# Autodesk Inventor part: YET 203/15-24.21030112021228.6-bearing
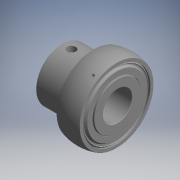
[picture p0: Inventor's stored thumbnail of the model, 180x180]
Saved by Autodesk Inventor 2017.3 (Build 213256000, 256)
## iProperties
Part Number: YET 203/15-24.21030112021228.6-bearing
Material: Generic
Catalog Web Link: www.cadenas.de
Description: ayf_001hc_hh_hy_bearing-Y-bearings
Vendor: SKF
Document SubType Name: Modeling
Designer: partserver
Manufacturer: SKF
Mass: 13.4334 g
Surface Area: 122.387 cm^2
Volume: 13.4334 cm^3
Density: 1 g/cm^3
Appearance: PSOLRGB-175-175-175
Category: PARTsolutions
Company: SKF
Title: YET 203/15-24.21030112021228.6-bearing
Author: Cadenas PARTsolutions
Comments: Y-bearings
PSOL_IDENT_0: {$CADENAS_DATA\23d-libs\skf\bearings_units_and_housings\bearing_units\ball_bearing_units\y-units\y-b
PSOL_IDENT_1: earing_square_flanged_units_parts\ayf_001hc_hh_hy_bearing.prj},235 {VTYP=3D},{NB=YET 203/15-24.21030
PSOL_IDENT_2: 112021228.6-bearing},{LINA=YET 203/15-24.21030112021228.6-bearing},{NN=ayf_001hc_hh_hy_bearing},{DAT
PSOL_IDENT_3: E=20.08.2020 13:45:20},{GEOMDATE=29.07.2020 17:09:33},{VERSION=},{LINEID=2150},{WBVAR=},{WBNUMERIC=}
PSOL_IDENT_4: {NB=YET 203/15-24.21030112021228.6-bearing},{LINA=YET 203/15-24.21030112021228.6-bearing},{KT=DUMM
PSOL_IDENT_5: Y},{PRODUCTID=103011202},{DESIGNATION=YET 203/15},{DD=15.0000},{D=40},{B=19.100},{C=12.000},{PITCH=2
PSOL_IDENT_6: 8.500},{DW=6.747},{FO=IEC_BBY_005},{DESIGN=ybrg2},{B1=28.600},{LM=Eccentric locking collar},{DES=Inn
PSOL_IDENT_7: er ring extended on one side},{PS=For agricultural applications},{MAT=},{SS=Standard seals},{UNIT=Me
PSOL_IDENT_8: tric},{G=MIN},{DD1=24.20},{DD2=27.20},{DD3=MIN},{B3=13.500},{B4=4.8},{BB4=MIN},{R12=0.3},{R12X=0},{S
PSOL_IDENT_9: S1=22.100},{NOTE=},{DG=MIN},{E=3.600},{F=1.300},{RG=MIN},{LOAD1=9.560},{LOAD2=4.750},{LOAD3=0.200},{
PSOL_IDENT_10: SPEED2=9500},{FF0=13},{BF=1},{A15=500000},{A8=400000},{A4=300000},{BETA=1.89},{SBT1=0.094},{SBT2=},{
PSOL_IDENT_11: RF1=0.00000039},{RF2=1.7},{SF1=0.00323},{SF2=36.5},{KZ=3.1},{II=1},{Z=8},{SG=VT307},{MASS=0.12},{G2=
PSOL_IDENT_12: M6x0.75},{HEX=3.000},{RTT=4},{MKIT=},{AS=},{TANGLE=},{SLEEVE=},{SRING=RIS 203},{FPC=RBC17_YBRG_003},
PSOL_IDENT_13: {POPI=1},{NOUN=N020},{NOUNDES=Ball bearing},{MOD=M200},{MODDES=Radial deep groove},{YZ=12.1},{PIM=YE
PSOL_IDENT_14: T 203/15},{LNDD11=MIN},{LUB3=0},{BZ=0.3502},{SDALG=h},{YRZ=17.6235},{SHAPE=1},{LNB1HM11=0},{LWM=0},{
PSOL_IDENT_15: TYPEID=103011},{LUBGR2=0},{LOCKNUT=},{LOCKDEVICE=},{LNB=MIN},{BB=MIN},{LNB1=MIN},{S1ALG=0},{HH=MIN},
PSOL_IDENT_16: {LDB=MIN},{LDDD1=MIN},{LDDD2=MIN},{LDM=MIN},{LDFF=MIN},{TP=4},{LNBHM11=0},{BBHM11=0},{LNDD1HM11=0},{
PSOL_IDENT_17: HELP=3},{HHHM11=0},{LUBGR1=0},{LWV=0},{S2=0},{LUB2=1},{BZ1=0.000},{HEX2=}
NB: YET 203/15-24.21030112021228.6-bearing
NN: ayf_001hc_hh_hy_bearing
NT: Y-bearings
NBSYN: $DESIGNATION.-$DD1.$PRODUCTID.$C.$B1.-bearing
LINA: YET 203/15-24.21030112021228.6-bearing
CATALOG: SKF
DESIGNATION: YET 203/15
DD: 15
D: 40
B: 19.1
C: 12
B1: 28.6
DD1: 24.2
LOAD1: 9.56
LOAD2: 4.75
LOAD3: 0.2
SPEED2: 9500
SUPPLIER: SKF
ARTICLENO: YET 203/15-24.21030112021228.6-bearing
BOMINFO: YET 203/15-24.21030112021228.6-bearing
CREATOR: CADENAS GmbH
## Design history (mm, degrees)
sketch "Sketch_1"
  geometry: L1 (12.3, 0)-(-6.2, 0); L2 (-6.2, 7.5)-(12.3, 7.5); L3 (12.6, 7.8)-(12.6, 11.45); L4 (12.45, 11.6)-(8.6, 11.6); L5 (8.6, 11.6)-(8.6, 12.1); L6 (8.6, 12.1)-(2.6, 12.1); L7 (-2.6, 12.1)-(-6.35, 12.1); L8 (-6.5, 11.95)-(-6.5, 7.8); A1 r 0.3 centre (-6.2, 7.8) between (-6.5, 7.8) and (-6.2, 7.5); A2 r 0.3 centre (12.3, 7.8) between (12.3, 7.5) and (12.6, 7.8); A3 r 0.15 centre (12.45, 11.45) between (12.6, 11.45) and (12.45, 11.6); A4 r 3.374 centre (0, 14.25) between (-2.6, 12.1) and (2.6, 12.1); A5 r 0.15 centre (-6.35, 11.95) between (-6.35, 12.1) and (-6.5, 11.95)
  constraints: 16 end point, 10 point on circle, 5 centre point
revolve "Revolution1" sketch "Sketch_1" stored, may be unused: angle "d0" = 360 deg
sketch "Sketch_4"
  geometry: L1 (50, 0)-(-50, 0); L2 (-6, 15.235)-(-6, 12.431); L3 (-6, 12.431)-(-5.65, 12.431); L4 (-5.65, 12.431)-(-5.65, 15.059); L5 (-5.65, 15.059)-(-4.88, 15.636); L6 (-4.88, 15.636)-(-4.838, 15.58); L7 (-4.838, 15.58)-(-5.58, 15.024); L8 (-5.58, 15.024)-(-5.58, 12.597); L9 (-5.58, 12.597)-(-4.961, 12.597); L10 (-4.961, 12.597)-(-5.066, 12.1); L11 (-5.066, 12.1)-(-4.716, 12.1); L12 (-4.716, 12.1)-(-4.599, 12.652); L13 (-4.599, 12.652)-(-4.599, 13.205); L14 (-4.599, 13.205)-(-5.066, 13.757); L15 (-5.066, 13.757)-(-5.066, 14.862); L16 (-5.066, 14.862)-(-4.599, 15.414); L17 (-4.599, 15.414)-(-4.599, 17.573); L18 (-4.649, 17.623)-(-4.899, 17.623); L19 (-4.949, 17.573)-(-5.568, 16.836); L20 (-5.568, 16.836)-(-5.3, 16.611); L21 (-5.3, 16.611)-(-4.949, 17.029); L22 (-4.949, 17.029)-(-4.949, 16.021); L23 (-4.949, 16.021)-(-6, 15.235); A1 r 0.05 centre (-4.649, 17.573) between (-4.599, 17.573) and (-4.649, 17.623); A2 r 0.05 centre (-4.899, 17.573) between (-4.899, 17.623) and (-4.949, 17.573)
  constraints: 46 end point, 4 point on circle, 2 centre point
revolve "Revolution2" sketch "Sketch_4" stored, may be unused: angle "d1" = 360 deg
sketch "Sketch_9"
  geometry: L1 (50, 0)-(-50, 0); L2 (4.599, 17.573)-(4.599, 15.414); L3 (4.599, 15.414)-(5.066, 14.862); L4 (5.066, 14.862)-(5.066, 13.757); L5 (5.066, 13.757)-(4.599, 13.205); L6 (4.599, 13.205)-(4.599, 12.652); L7 (4.599, 12.652)-(4.716, 12.1); L8 (4.716, 12.1)-(5.066, 12.1); L9 (5.066, 12.1)-(4.961, 12.597); L10 (4.961, 12.597)-(5.58, 12.597); L11 (5.58, 12.597)-(5.58, 15.024); L12 (5.58, 15.024)-(4.838, 15.58); L13 (4.838, 15.58)-(4.88, 15.636); L14 (4.88, 15.636)-(5.65, 15.059); L15 (5.65, 15.059)-(5.65, 12.431); L16 (5.65, 12.431)-(6, 12.431); L17 (6, 12.431)-(6, 15.235); L18 (6, 15.235)-(4.949, 16.021); L19 (4.949, 16.021)-(4.949, 17.029); L20 (4.949, 17.029)-(5.3, 16.611); L21 (5.3, 16.611)-(5.568, 16.836); L22 (5.568, 16.836)-(4.949, 17.573); L23 (4.899, 17.623)-(4.649, 17.623); A1 r 0.05 centre (4.899, 17.573) between (4.949, 17.573) and (4.899, 17.623); A2 r 0.05 centre (4.649, 17.573) between (4.649, 17.623) and (4.599, 17.573)
  constraints: 46 end point, 4 point on circle, 2 centre point
revolve "Revolution3" sketch "Sketch_9" stored, may be unused: angle "d2" = 360 deg
sketch "Sketch_14"
  geometry: L1 (6, 0)-(-6, 0); L2 (-6, 17.448)-(-5.023, 17.448); L3 (-5.023, 17.448)-(-4.919, 17.525); L4 (-4.569, 17.44)-(-4.464, 16.949); L5 (-4.464, 16.949)-(-2.024, 16.949); L6 (2.024, 16.949)-(4.464, 16.949); L7 (4.464, 16.949)-(4.569, 17.44); L8 (4.889, 17.555)-(5.023, 17.448); L9 (5.023, 17.448)-(6, 17.448); L10 (6, 17.448)-(6, 19.005); L11 (-6, 19.005)-(-6, 17.448); A1 r 0.2 centre (-4.764, 17.398) between (-4.569, 17.44) and (-4.919, 17.525); A2 r 3.373 centre (0, 14.25) between (2.024, 16.949) and (-2.024, 16.949); A3 r 0.2 centre (4.764, 17.398) between (4.889, 17.555) and (4.569, 17.44); A4 r 0.1 centre (5.9, 19.005) between (6, 19.005) and (5.93, 19.101); A5 r 20 centre (0, 0) between (5.93, 19.101) and (-5.93, 19.101); A6 r 0.1 centre (-5.9, 19.005) between (-5.93, 19.101) and (-6, 19.005)
  constraints: 22 end point, 12 point on circle, 6 centre point
revolve "Revolution4" sketch "Sketch_14" stored, may be unused: angle "d3" = 360 deg
sketch "Sketch_15"
  geometry: L1 (-2.1, 21)-(-2.1, 14.25); L2 (-2.1, 14.25)-(-2.75, 14.25); L3 (-2.75, 14.25)-(-2.75, 21); L4 (-2.75, 21)-(-2.1, 21); L5 (-2.1, 21)-(-2.1, 14.25)
  constraints: 10 end point
revolve "Revolution5" sketch "Sketch_15" stored, may be unused: angle "d4" = 360 deg
sketch "Sketch_16"
  geometry: L1 (-3.6, 21)-(-3.6, 14.25); L2 (-3.6, 14.25)-(-4.25, 14.25); L3 (-4.25, 14.25)-(-4.25, 21); L4 (-4.25, 21)-(-3.6, 21); L5 (-3.6, 21)-(-3.6, 14.25)
  constraints: 10 end point
revolve "Revolution6" sketch "Sketch_16" stored, may be unused: angle "d5" = 360 deg
sketch "Sketch_17"
  geometry: L1 (21.8, 0)-(12.9, 0); L2 (8.6, 13.3)-(8.6, 12.25); L3 (8.6, 12.25)-(8.75, 12.1); L4 (8.75, 12.1)-(12.6, 12.1); L5 (12.6, 12.1)-(12.6, 7.8); L6 (12.6, 7.8)-(12.9, 7.5); L7 (12.9, 7.5)-(21.8, 7.5); L8 (21.8, 7.5)-(22.1, 7.8); L9 (22.1, 7.8)-(22.1, 13.45); L10 (21.95, 13.6)-(8.9, 13.6); A1 r 0.15 centre (21.95, 13.45) between (22.1, 13.45) and (21.95, 13.6); A2 r 0.3 centre (8.9, 13.3) between (8.9, 13.6) and (8.6, 13.3)
  constraints: 20 end point, 4 point on circle, 2 centre point
revolve "Revolution7" sketch "Sketch_17" stored, may be unused: angle "d6" = 360 deg
sketch "Sketch_18"
  geometry: L1 (17.3, 7.5)-(17.3, 13.905); L2 (17.3, 13.905)-(20.3, 13.905); L3 (20.3, 13.905)-(20.3, 7.5); L4 (20.3, 7.5)-(17.3, 7.5); L5 (17.3, 7.5)-(17.3, 13.905)
  constraints: 10 end point
revolve "Revolution8" sketch "Sketch_18" stored, may be unused: angle "d7" = 360 deg
sketch "Sketch_19"
  geometry: L1 (-1.5, -0.866)-(0, -1.732); L2 (0, -1.732)-(1.5, -0.866); L3 (1.5, -0.866)-(1.5, 0.866); L4 (1.5, 0.866)-(0, 1.732); L5 (0, 1.732)-(-1.5, 0.866); L6 (-1.5, 0.866)-(-1.5, -0.866)
  constraints: 12 end point
extrude "Extrusion1" cut sketch "Sketch_19" distance "d8" = 0.61; taper "d9" = 0 deg
sketch "Sketch_20"
  geometry: L1 (-17.3, -9.303)-(-17.3, -13.905); L2 (-17.3, -13.905)-(-19.46, -13.905); L3 (-19.46, -13.905)-(-19.46, -10.55); L4 (-19.46, -10.55)-(-17.3, -9.303); L5 (-17.3, -9.303)-(-17.3, -13.905)
  constraints: 10 end point
revolve "Revolution9" sketch "Sketch_20" stored, may be unused: angle "d10" = 360 deg
node "ball_1_XY"
node "ball_1_YZ"
node "ball_1_ZX"
node "ball_1_X"
node "ball_1_Y"
node "ball_1_Z"
node "ball_1_Center"
node "ball_2_XY"
node "ball_2_YZ"
node "ball_2_ZX"
node "ball_2_X"
node "ball_2_Y"
node "ball_2_Z"
node "ball_2_Center"
node "ball_3_XY"
node "ball_3_YZ"
node "ball_3_ZX"
node "ball_3_X"
node "ball_3_Y"
node "ball_3_Z"
node "ball_3_Center"
node "ball_4_XY"
node "ball_4_YZ"
node "ball_4_ZX"
node "ball_4_X"
node "ball_4_Y"
node "ball_4_Z"
node "ball_4_Center"
node "ball_5_XY"
node "ball_5_YZ"
node "ball_5_ZX"
node "ball_5_X"
node "ball_5_Y"
node "ball_5_Z"
node "ball_5_Center"
node "ball_6_XY"
node "ball_6_YZ"
node "ball_6_ZX"
node "ball_6_X"
node "ball_6_Y"
node "ball_6_Z"
node "ball_6_Center"
node "ball_7_XY"
node "ball_7_YZ"
node "ball_7_ZX"
node "ball_7_X"
node "ball_7_Y"
node "ball_7_Z"
node "ball_7_Center"
node "ball_8_XY"
node "ball_8_YZ"
node "ball_8_ZX"
node "ball_8_X"
node "ball_8_Y"
node "ball_8_Z"
node "ball_8_Center"
node "brg_XY"
node "brg_YZ"
node "brg_ZX"
node "brg_X"
node "brg_Y"
node "brg_Z"
node "brg_Center"
node "brg3_XY"
node "brg3_YZ"
node "brg3_ZX"
node "brg3_X"
node "brg3_Y"
node "brg3_Z"
node "brg3_Center"
body "Solid1"
other parameters: "d11" = 0
